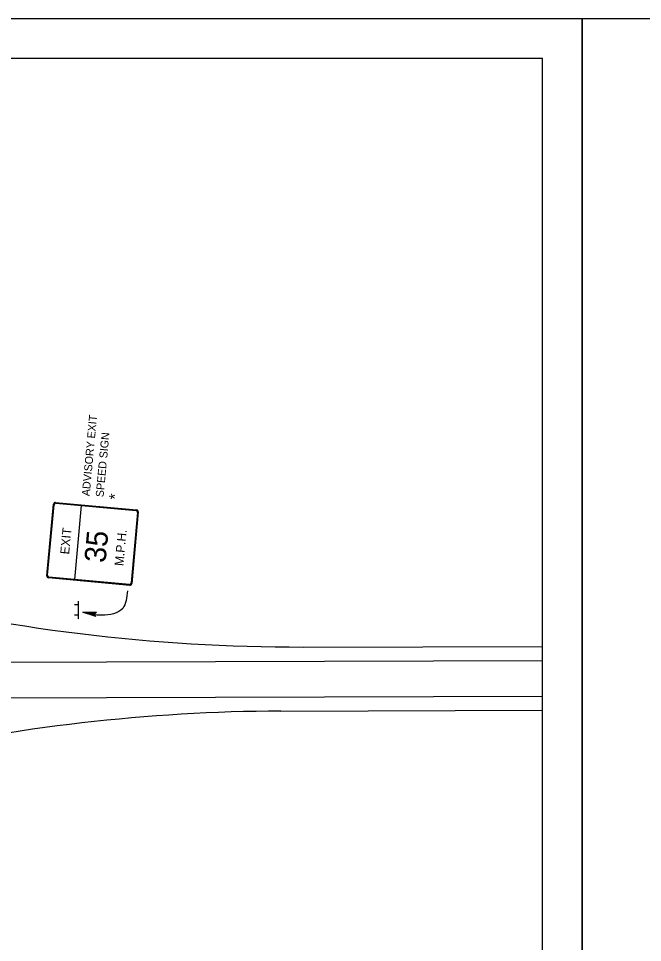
# Model space of a CAD drawing. Extents: x 644898 to 648326, y 298294 to 300670.
# Drawn here: x 647208.5 to 647444.1, y 300321.7 to 300670.5 of the extents above; entities that cross this region are included whole.
import ezdxf

# ---------------------------------------------------------------- set-up
doc = ezdxf.new("R2010")
doc.units = 0
for name, color, linetype in [('1', 7, 'Continuous'), ('2', 7, 'Continuous'), ('XCS-GRID-MIN', 7, 'Continuous')]:
    doc.layers.add(name, color=color, linetype=linetype)

msp = doc.modelspace()

# ---------------------------------------------------------------- linework, layer by layer
at = {"layer": '1'}
for p in [(646620.32, 300655.49), (647406.32, 300091.49)]:
    msp.add_line(p, (647406.32, 300655.49), dxfattribs=at)
at = {"layer": '2'}
for p, q in [((647219.2, 300460.12), (647221.7, 300487.24)), ((647219.45, 300460.37), (647221.95, 300486.99)), ((647222.45, 300487.87), (647253.07, 300484.99)), ((647222.57, 300487.62), (647252.95, 300484.74)), ((647229.7, 300458.74), (647232.2, 300486.62)), ((647253.45, 300483.99), (647250.95, 300457.49)), ((647253.7, 300484.24), (647251.2, 300457.24)), ((647250.45, 300456.49), (647219.82, 300459.37)), ((647250.32, 300456.87), (647219.95, 300459.62)), ((647230.95, 300449.24), (647229.57, 300449.24)), ((647230.95, 300450.62), (647230.95, 300443.87)), ((647230.95, 300445.24), (647229.57, 300445.24)), ((647230.95, 300443.49), (647230.95, 300443.49)), ((647230.95, 300443.49), (647230.95, 300443.49)), ((647315.95, 300433.24), (647406.32, 300433.51)), ((647401.07, 300433.49), (647401.07, 300433.49)), ((647003.32, 300426.99), (647406.32, 300428.13)), ((647005.32, 300413.49), (647406.32, 300414.76)), ((647307.57, 300409.12), (647406.32, 300409.38))]:
    msp.add_line(p, q, dxfattribs=at)
msp.add_lwpolyline([(647237.45, 300444.99), (647237.32, 300445.37), (647232.82, 300446.37), (647237.45, 300444.99), (647237.7, 300444.74), (647232.82, 300446.37), (647237.45, 300445.87), (647237.7, 300446.12), (647232.82, 300446.37), (647237.95, 300446.37), (647237.7, 300446.12)], dxfattribs=at)
for centre, start, end in [((647313.92, 301105.15), 255.77937, 270.1682), ((647309.55, 299737.19), 90.1683, 103.0152)]:
    msp.add_arc(centre, 671.88, start, end, dxfattribs=at)
for centre, major_axis, start_param, end_param in [((647222.35, 300487.14), (-0.066, -0.711), 3.141593, 4.712389), ((647222.51, 300486.91), (-0.06, -0.652), 3.141593, 4.712389), ((647252.86, 300484.1), (0.06, 0.652), 4.712389, 6.283185), ((647253.07, 300484.29), (0.066, 0.711), 4.712389, 6.283185), ((647219.84, 300460.11), (-0.066, -0.711), 4.712389, 6.283185), ((647220.05, 300460.3), (-0.06, -0.652), 4.712389, 6.283185), ((647250.39, 300457.49), (0.06, 0.652), 3.141593, 4.712389), ((647250.56, 300457.26), (-0.066, -0.711), 0, 1.570796)]:
    msp.add_ellipse(centre, major_axis=major_axis, ratio=0.9, start_param=start_param, end_param=end_param, dxfattribs=at)
msp.add_spline([(647249.57, 300454.49), (647247.82, 300447.87), (647239.95, 300445.24), (647232.82, 300446.37)], degree=3, dxfattribs=at)
at = {"layer": 'XCS-GRID-MIN'}
for points in [[(646580.32, 300670.49), (647421.32, 300670.49), (647421.32, 300076.49), (646580.32, 300076.49)], [(647421.32, 300670.49), (648262.32, 300670.49), (648262.32, 300076.49), (647421.32, 300076.49)]]:
    msp.add_lwpolyline(points, close=True, dxfattribs=at)

# ---------------------------------------------------------------- texts
at = {"layer": '2'}
for s, height, rotation, p in [('ADVISORY EXIT', 3, 84.7025, (647235.32, 300490.12)), ('SPEED SIGN', 3, 84.7025, (647240.57, 300489.74)), ('*', 4.32, 84.7025, (647246.89, 300488.68)), ('EXIT', 3.373, 84.7024, (647227.57, 300468.12)), ('35', 8.062, 84.7025, (647241.32, 300464.87)), ('M.P.H.', 3.373, 84.7031, (647248.07, 300463.74))]:
    msp.add_text(s, height=height, rotation=rotation, dxfattribs=at).set_placement(p)

doc.saveas('drawing.dxf')
